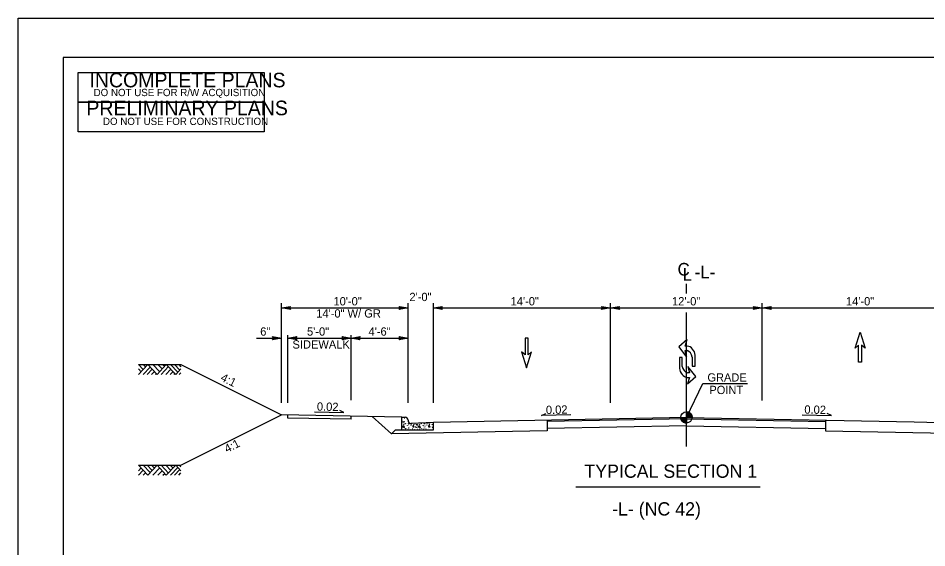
# Model space of a CAD drawing. Extents: x 1901670 to 1902225, y 193498 to 194278.
# Drawn here: x 1901670 to 1901741.8, y 194145.5 to 194187.3 of the extents above; entities that cross this region are included whole.
import ezdxf

# ---------------------------------------------------------------- set-up
doc = ezdxf.new("R2010")
doc.units = 0
for name, color, linetype in [('MARK BIKE LEFT ARROW CELL', 7, 'Continuous'), ('Old_Level_1', 7, 'Continuous'), ('Old_Level_10', 7, 'Continuous'), ('Old_Level_2', 7, 'Continuous'), ('Prop Dimension', 7, 'Continuous'), ('Prop Dimension Text', 7, 'Continuous'), ('Scratch_Level_0', 7, 'Continuous'), ('Sheet Sticker Incomplete CELL', 7, 'Continuous'), ('Sheet Sticker Preliminary CELL', 7, 'Continuous'), ('Typical Curb CELL', 7, 'Continuous'), ('Typical Pavement Slope CELL', 7, 'Continuous'), ('Typical Terminator CELL', 7, 'Continuous'), ('Typical Text Grade Point CELL', 7, 'Continuous')]:
    doc.layers.add(name, color=color, linetype=linetype)

# ---------------------------------------------------------------- blocks, each defined once
blk = doc.blocks.new('TERMINATOR')
at = {"layer": 'Typical Terminator CELL'}
blk.add_lwpolyline([(-0.469, 0.081), (0, 0), (-0.471, -0.083), (-0.411, 0)], close=True, dxfattribs=at)

msp = doc.modelspace()

# ---------------------------------------------------------------- linework, layer by layer
at = {"layer": 'MARK BIKE LEFT ARROW CELL'}
for p, q in [((1901722.83, 194161.908), (1901722.179, 194161.323)), ((1901722.83, 194161.908), (1901722.179, 194161.323)), ((1901722.678, 194161.399), (1901722.83, 194161.908)), ((1901722.678, 194161.399), (1901722.83, 194161.908)), ((1901722.179, 194161.323), (1901722.795, 194160.514)), ((1901722.179, 194161.323), (1901722.795, 194160.514)), ((1901722.852, 194161.4), (1901722.678, 194161.399)), ((1901722.852, 194161.4), (1901722.678, 194161.399)), ((1901722.455, 194160.499), (1901722.224, 194160.499)), ((1901722.224, 194160.499), (1901722.224, 194159.639)), ((1901722.455, 194160.499), (1901722.224, 194160.499)), ((1901722.224, 194160.499), (1901722.224, 194159.639)), ((1901722.455, 194159.793), (1901722.455, 194160.499)), ((1901722.455, 194159.793), (1901722.455, 194160.499)), ((1901722.795, 194160.514), (1901722.678, 194161.034)), ((1901722.678, 194161.034), (1901722.833, 194161.034)), ((1901722.795, 194160.514), (1901722.678, 194161.034)), ((1901722.678, 194161.034), (1901722.833, 194161.034)), ((1901723.244, 194160.515), (1901723.244, 194159.808)), ((1901723.244, 194160.515), (1901723.244, 194159.808)), ((1901723.475, 194159.808), (1901723.475, 194160.669)), ((1901723.475, 194159.808), (1901723.475, 194160.669)), ((1901723.519, 194158.984), (1901722.904, 194159.793)), ((1901722.904, 194159.793), (1901723.02, 194159.273)), ((1901723.519, 194158.984), (1901722.904, 194159.793)), ((1901722.904, 194159.793), (1901723.02, 194159.273)), ((1901723.244, 194159.808), (1901723.475, 194159.808)), ((1901723.244, 194159.808), (1901723.475, 194159.808)), ((1901723.02, 194159.273), (1901722.865, 194159.273)), ((1901723.02, 194159.273), (1901722.865, 194159.273)), ((1901722.869, 194158.399), (1901723.519, 194158.984)), ((1901722.869, 194158.399), (1901723.519, 194158.984)), ((1901722.846, 194158.908), (1901723.02, 194158.908)), ((1901722.846, 194158.908), (1901723.02, 194158.908)), ((1901723.02, 194158.908), (1901722.869, 194158.399)), ((1901723.02, 194158.908), (1901722.869, 194158.399))]:
    msp.add_line(p, q, dxfattribs=at)
for centre, major_axis, ratio in [((1901722.917, 194160.733), (-0.294, 0.632), 0.75825), ((1901722.917, 194160.733), (-0.294, 0.632), 0.75825), ((1901722.897, 194160.579), (-0.204, 0.44), 0.652763), ((1901722.897, 194160.579), (-0.204, 0.44), 0.652763), ((1901722.782, 194159.574), (0.294, -0.632), 0.75825), ((1901722.782, 194159.574), (0.294, -0.632), 0.75825), ((1901722.801, 194159.728), (0.204, -0.44), 0.652763), ((1901722.801, 194159.728), (0.204, -0.44), 0.652763)]:
    msp.add_ellipse(centre, major_axis=major_axis, ratio=ratio, start_param=4.277405, end_param=5.848201, dxfattribs=at)
at = {"layer": 'Old_Level_1'}
for p, q in [((1901722.78, 194165.552), (1901722.78, 194166.32)), ((1901722.78, 194153.466), (1901722.78, 194164.037)), ((1901679.481, 194159.946), (1901679.856, 194159.543)), ((1901679.481, 194159.141), (1901680.223, 194159.938)), ((1901679.855, 194159.141), (1901680.409, 194159.737)), ((1901679.856, 194159.946), (1901680.043, 194159.745)), ((1901680.223, 194159.938), (1901680.947, 194159.159)), ((1901680.614, 194159.946), (1901681.147, 194159.373)), ((1901680.947, 194159.159), (1901681.678, 194159.945)), ((1901681.012, 194159.946), (1901681.345, 194159.587)), ((1901681.257, 194159.141), (1901681.843, 194159.769)), ((1901681.414, 194159.946), (1901681.547, 194159.803)), ((1901681.678, 194159.945), (1901682.419, 194159.149)), ((1901682, 194159.946), (1901682.58, 194159.323)), ((1901682.333, 194159.946), (1901682.747, 194159.502)), ((1901682.653, 194159.946), (1901682.823, 194159.763)), ((1901679.481, 194159.584), (1901679.687, 194159.362)), ((1901680.164, 194159.141), (1901680.565, 194159.57)), ((1901680.511, 194159.141), (1901680.738, 194159.384)), ((1901680.822, 194159.141), (1901680.893, 194159.217)), ((1901681.627, 194159.141), (1901682.027, 194159.57)), ((1901681.993, 194159.141), (1901682.21, 194159.374)), ((1901682.288, 194159.141), (1901682.357, 194159.215)), ((1901682.419, 194159.149), (1901682.823, 194159.584)), ((1901682.689, 194159.141), (1901682.823, 194159.284)), ((1901693.395, 194156.187), (1901695.71, 194156.139)), ((1901695.71, 194156.139), (1901695.377, 194156.306)), ((1901711.327, 194155.904), (1901711.66, 194156.071)), ((1901722.78, 194155.761), (1901722.78, 194156.211)), ((1901734.234, 194155.904), (1901733.901, 194156.071)), ((1901697.952, 194155.824), (1901699.474, 194154.462)), ((1901722.78, 194155.761), (1901702.78, 194155.361)), ((1901713.642, 194155.952), (1901711.327, 194155.904)), ((1901722.782, 194155.657), (1901711.782, 194155.437)), ((1901711.782, 194155.541), (1901711.782, 194154.708)), ((1901722.33, 194155.761), (1901722.78, 194155.761)), ((1901722.779, 194155.311), (1901722.78, 194155.761)), ((1901722.78, 194155.761), (1901722.779, 194155.311)), ((1901723.23, 194155.761), (1901722.78, 194155.761)), ((1901722.78, 194155.761), (1901740.78, 194155.401)), ((1901722.782, 194155.657), (1901733.782, 194155.437)), ((1901731.919, 194155.952), (1901734.234, 194155.904)), ((1901733.782, 194155.541), (1901733.782, 194154.708)), ((1901740.78, 194155.401), (1901742.78, 194155.361)), ((1901699.781, 194154.768), (1901699.474, 194154.462)), ((1901711.782, 194154.708), (1901699.474, 194154.462)), ((1901699.781, 194154.768), (1901700.281, 194154.778)), ((1901722.782, 194155.095), (1901711.782, 194154.875)), ((1901722.782, 194155.095), (1901733.782, 194154.875)), ((1901733.782, 194154.708), (1901746.086, 194154.462)), ((1901679.481, 194151.989), (1901680.223, 194151.192)), ((1901679.481, 194151.546), (1901679.687, 194151.768)), ((1901679.855, 194151.989), (1901680.409, 194151.393)), ((1901680.164, 194151.989), (1901680.565, 194151.56)), ((1901680.223, 194151.192), (1901680.947, 194151.971)), ((1901680.511, 194151.989), (1901680.738, 194151.746)), ((1901680.614, 194151.184), (1901681.147, 194151.757)), ((1901680.822, 194151.989), (1901680.893, 194151.913)), ((1901680.947, 194151.971), (1901681.678, 194151.185)), ((1901681.257, 194151.989), (1901681.843, 194151.361)), ((1901681.627, 194151.989), (1901682.027, 194151.56)), ((1901681.678, 194151.185), (1901682.419, 194151.981)), ((1901681.993, 194151.989), (1901682.21, 194151.756)), ((1901682, 194151.184), (1901682.58, 194151.807)), ((1901682.288, 194151.989), (1901682.357, 194151.915)), ((1901682.419, 194151.981), (1901682.823, 194151.546)), ((1901682.689, 194151.989), (1901682.823, 194151.846)), ((1901679.481, 194151.184), (1901679.856, 194151.587)), ((1901679.856, 194151.184), (1901680.043, 194151.385)), ((1901681.012, 194151.184), (1901681.345, 194151.543)), ((1901681.414, 194151.184), (1901681.547, 194151.327)), ((1901682.333, 194151.184), (1901682.747, 194151.628)), ((1901682.653, 194151.184), (1901682.823, 194151.367)), ((1901714.048, 194150.258), (1901728.608, 194150.258))]:
    msp.add_line(p, q, dxfattribs=at)
for points in [[(1901722.784, 194156.211), (1901722.784, 194156.211), (1901722.784, 194155.761)], [(1901722.793, 194156.211), (1901722.793, 194155.761)], [(1901722.802, 194156.21), (1901722.802, 194155.761)], [(1901722.811, 194156.21), (1901722.811, 194155.761)], [(1901722.82, 194156.209), (1901722.82, 194155.761)], [(1901722.829, 194156.208), (1901722.829, 194155.761)], [(1901722.838, 194156.207), (1901722.838, 194155.761)], [(1901722.847, 194156.206), (1901722.847, 194155.761)], [(1901722.856, 194156.205), (1901722.856, 194155.761)], [(1901722.865, 194156.203), (1901722.865, 194155.761)], [(1901722.874, 194156.201), (1901722.874, 194155.761)], [(1901722.883, 194156.199), (1901722.883, 194155.761)], [(1901722.892, 194156.197), (1901722.892, 194155.761)], [(1901722.901, 194156.194), (1901722.901, 194155.761)], [(1901722.91, 194156.192), (1901722.91, 194155.761)], [(1901722.919, 194156.189), (1901722.919, 194155.761)], [(1901722.928, 194156.186), (1901722.928, 194155.761)], [(1901722.937, 194156.183), (1901722.937, 194155.761)], [(1901722.946, 194156.179), (1901722.946, 194155.761)], [(1901722.955, 194156.175), (1901722.955, 194155.761)], [(1901722.964, 194156.171), (1901722.964, 194155.761)], [(1901722.973, 194156.167), (1901722.973, 194155.761)], [(1901722.982, 194156.163), (1901722.982, 194155.761)], [(1901722.991, 194156.158), (1901722.991, 194155.761)], [(1901723, 194156.153), (1901723, 194155.761)], [(1901723.009, 194156.148), (1901723.009, 194155.761)], [(1901723.018, 194156.143), (1901723.018, 194155.761)], [(1901723.027, 194156.137), (1901723.027, 194155.761)], [(1901723.036, 194156.131), (1901723.036, 194155.761)], [(1901723.045, 194156.124), (1901723.045, 194155.761)], [(1901723.054, 194156.118), (1901723.054, 194155.761)], [(1901723.063, 194156.111), (1901723.063, 194155.761)], [(1901723.072, 194156.103), (1901723.072, 194155.761)], [(1901723.081, 194156.095), (1901723.081, 194155.761)], [(1901723.09, 194156.087), (1901723.09, 194155.761)], [(1901723.099, 194156.078), (1901723.099, 194155.761)], [(1901723.108, 194156.069), (1901723.108, 194155.761)], [(1901723.117, 194156.059), (1901723.117, 194155.761)], [(1901723.126, 194156.048), (1901723.126, 194155.761)], [(1901722.332, 194155.761), (1901722.332, 194155.712)], [(1901722.341, 194155.761), (1901722.341, 194155.659)], [(1901722.35, 194155.761), (1901722.35, 194155.627)], [(1901722.359, 194155.761), (1901722.359, 194155.6)], [(1901722.368, 194155.761), (1901722.368, 194155.579)], [(1901722.377, 194155.761), (1901722.377, 194155.56)], [(1901722.386, 194155.761), (1901722.386, 194155.543)], [(1901722.395, 194155.761), (1901722.395, 194155.527)], [(1901722.404, 194155.761), (1901722.404, 194155.513)], [(1901722.413, 194155.761), (1901722.413, 194155.5)], [(1901722.422, 194155.761), (1901722.422, 194155.488)], [(1901722.431, 194155.761), (1901722.431, 194155.477)], [(1901722.44, 194155.761), (1901722.44, 194155.466)], [(1901722.449, 194155.761), (1901722.449, 194155.456)], [(1901722.458, 194155.761), (1901722.458, 194155.446)], [(1901722.467, 194155.761), (1901722.467, 194155.437)], [(1901722.476, 194155.761), (1901722.476, 194155.429)], [(1901722.485, 194155.761), (1901722.485, 194155.421)], [(1901722.494, 194155.761), (1901722.494, 194155.413)], [(1901722.503, 194155.761), (1901722.503, 194155.406)], [(1901722.512, 194155.761), (1901722.512, 194155.399)], [(1901722.521, 194155.761), (1901722.521, 194155.393)], [(1901722.53, 194155.761), (1901722.53, 194155.387)], [(1901722.539, 194155.761), (1901722.539, 194155.381)], [(1901722.548, 194155.761), (1901722.548, 194155.375)], [(1901722.557, 194155.761), (1901722.557, 194155.37)], [(1901722.566, 194155.761), (1901722.566, 194155.365)], [(1901722.575, 194155.761), (1901722.575, 194155.36)], [(1901722.584, 194155.761), (1901722.584, 194155.356)], [(1901722.593, 194155.761), (1901722.593, 194155.352)], [(1901722.602, 194155.761), (1901722.602, 194155.348)], [(1901722.611, 194155.761), (1901722.611, 194155.344)], [(1901722.62, 194155.761), (1901722.62, 194155.34)], [(1901722.629, 194155.761), (1901722.629, 194155.337)], [(1901722.638, 194155.761), (1901722.638, 194155.334)], [(1901722.647, 194155.761), (1901722.647, 194155.331)], [(1901722.656, 194155.761), (1901722.656, 194155.329)], [(1901722.665, 194155.761), (1901722.665, 194155.326)], [(1901722.674, 194155.761), (1901722.674, 194155.324)], [(1901722.683, 194155.761), (1901722.683, 194155.322)], [(1901722.692, 194155.761), (1901722.692, 194155.32)], [(1901722.701, 194155.761), (1901722.701, 194155.318)], [(1901722.71, 194155.761), (1901722.71, 194155.317)], [(1901722.719, 194155.761), (1901722.719, 194155.315)], [(1901722.728, 194155.761), (1901722.728, 194155.314)], [(1901722.737, 194155.761), (1901722.737, 194155.313)], [(1901722.746, 194155.761), (1901722.746, 194155.312)], [(1901722.755, 194155.761), (1901722.755, 194155.312)], [(1901722.764, 194155.761), (1901722.764, 194155.311)], [(1901722.773, 194155.761), (1901722.773, 194155.311), (1901722.773, 194155.311)], [(1901723.135, 194156.037), (1901723.135, 194155.761)], [(1901723.144, 194156.025), (1901723.144, 194155.761)], [(1901723.153, 194156.012), (1901723.153, 194155.761)], [(1901723.162, 194155.998), (1901723.162, 194155.761)], [(1901723.171, 194155.983), (1901723.171, 194155.761)], [(1901723.18, 194155.967), (1901723.18, 194155.761)], [(1901723.189, 194155.948), (1901723.189, 194155.761)], [(1901723.198, 194155.927), (1901723.198, 194155.761)], [(1901723.207, 194155.902), (1901723.207, 194155.761)], [(1901723.216, 194155.871), (1901723.216, 194155.761)], [(1901723.225, 194155.825), (1901723.225, 194155.761)]]:
    msp.add_lwpolyline(points, dxfattribs=at)
msp.add_circle((1901722.78, 194155.761), 0.45, dxfattribs=at)
for start, end in [(359.99048, 89.99048), (179.99048, 269.99048)]:
    msp.add_arc((1901722.78, 194155.761), 0.45, start, end, dxfattribs=at)
at = {"layer": 'Old_Level_10'}
msp.add_lwpolyline([(1901673.525, 194104.872), (1901776.645, 194104.872), (1901776.645, 194184.208), (1901673.525, 194184.208)], close=True, dxfattribs=at)
at = {"layer": 'Prop Dimension'}
for p, q in [((1901690.78, 194156.899), (1901690.78, 194164.781)), ((1901700.78, 194156.899), (1901700.78, 194164.781)), ((1901702.78, 194156.899), (1901702.78, 194164.781)), ((1901716.78, 194156.899), (1901716.78, 194164.781)), ((1901728.78, 194157.09), (1901728.78, 194164.781)), ((1901690.78, 194164.411), (1901700.78, 194164.411)), ((1901702.78, 194164.411), (1901716.78, 194164.411)), ((1901716.78, 194164.411), (1901728.78, 194164.411)), ((1901728.78, 194164.411), (1901742.78, 194164.411)), ((1901688.815, 194162.021), (1901690.78, 194162.021)), ((1901691.28, 194156.899), (1901691.28, 194162.248)), ((1901691.28, 194162.021), (1901696.28, 194162.021)), ((1901696.28, 194157.12), (1901696.28, 194162.248)), ((1901696.28, 194162.021), (1901700.78, 194162.021))]:
    msp.add_line(p, q, dxfattribs=at)
for points in [[(1901710.545, 194160.941), (1901710.274, 194160.691), (1901710.274, 194162.025), (1901710.024, 194162.025), (1901710.024, 194160.691), (1901709.753, 194160.941), (1901710.149, 194159.67)], [(1901710.545, 194160.941), (1901710.274, 194160.691), (1901710.274, 194162.025), (1901710.024, 194162.025), (1901710.024, 194160.691), (1901709.753, 194160.941), (1901710.149, 194159.67)], [(1901736.901, 194161.22), (1901736.63, 194161.47), (1901736.63, 194160.136), (1901736.38, 194160.136), (1901736.38, 194161.47), (1901736.11, 194161.22), (1901736.505, 194162.49)], [(1901736.901, 194161.22), (1901736.63, 194161.47), (1901736.63, 194160.136), (1901736.38, 194160.136), (1901736.38, 194161.47), (1901736.11, 194161.22), (1901736.505, 194162.49)]]:
    msp.add_lwpolyline(points, close=True, dxfattribs=at)
at = {"layer": 'Scratch_Level_0'}
msp.add_lwpolyline([(1901669.969, 194187.31), (1901779.969, 194187.31), (1901779.969, 194102.31), (1901669.969, 194102.31)], close=True, dxfattribs=at)
at = {"layer": 'Sheet Sticker Incomplete CELL'}
msp.add_lwpolyline([(1901674.711, 194180.674), (1901674.711, 194183.024), (1901689.411, 194183.024), (1901689.411, 194180.674)], close=True, dxfattribs=at)
at = {"layer": 'Sheet Sticker Preliminary CELL'}
msp.add_lwpolyline([(1901674.711, 194178.324), (1901674.711, 194180.674), (1901689.411, 194180.674), (1901689.411, 194178.324)], close=True, dxfattribs=at)
at = {"layer": 'Typical Curb CELL'}
for p, q in [((1901700.281, 194154.778), (1901700.281, 194155.778)), ((1901700.281, 194155.778), (1901700.541, 194155.778)), ((1901700.317, 194155.4), (1901700.471, 194155.445)), ((1901700.455, 194155.354), (1901700.317, 194155.4)), ((1901700.471, 194155.445), (1901700.455, 194155.354)), ((1901700.781, 194155.528), (1901700.781, 194155.538)), ((1901702.78, 194155.361), (1901701.03, 194155.288)), ((1901702.78, 194154.778), (1901702.78, 194155.361)), ((1901700.281, 194154.778), (1901702.78, 194154.778)), ((1901700.443, 194155.081), (1901700.34, 194155.006)), ((1901700.34, 194155.006), (1901700.506, 194154.966)), ((1901700.506, 194154.966), (1901700.443, 194155.081)), ((1901701.185, 194155.137), (1901701.15, 194155.024)), ((1901701.15, 194155.024), (1901701.27, 194155.018)), ((1901701.27, 194155.018), (1901701.185, 194155.137)), ((1901701.692, 194155.081), (1901701.589, 194155.006)), ((1901701.589, 194155.006), (1901701.754, 194154.966)), ((1901701.754, 194154.966), (1901701.692, 194155.081)), ((1901702.433, 194155.137), (1901702.399, 194155.024)), ((1901702.399, 194155.024), (1901702.52, 194155.018)), ((1901702.52, 194155.018), (1901702.433, 194155.137))]:
    msp.add_line(p, q, dxfattribs=at)
for centre in [(1901700.294, 194155.668), (1901700.345, 194155.485), (1901700.511, 194155.702), (1901702.439, 194155.32), (1901700.425, 194154.824), (1901700.442, 194155.212), (1901700.562, 194155.263), (1901700.597, 194154.864), (1901700.739, 194155.098), (1901700.774, 194154.801), (1901700.819, 194155.291), (1901700.831, 194154.915), (1901700.836, 194155.241), (1901700.865, 194155.069), (1901700.945, 194154.83), (1901701.013, 194155.155), (1901701.042, 194155.257), (1901701.15, 194154.852), (1901701.236, 194155.218), (1901701.31, 194154.784), (1901701.333, 194155.272), (1901701.361, 194155.018), (1901701.442, 194155.178), (1901701.458, 194154.972), (1901701.498, 194155.212), (1901701.515, 194155.115), (1901701.52, 194154.807), (1901701.674, 194154.824), (1901701.692, 194155.212), (1901701.812, 194155.263), (1901701.846, 194154.864), (1901701.988, 194155.098), (1901702.023, 194154.801), (1901702.068, 194155.291), (1901702.08, 194154.915), (1901702.085, 194155.241), (1901702.114, 194155.069), (1901702.194, 194154.83), (1901702.262, 194155.155), (1901702.291, 194155.257), (1901702.399, 194154.852), (1901702.485, 194155.218), (1901702.559, 194154.784), (1901702.582, 194155.303), (1901702.611, 194155.018), (1901702.691, 194155.178), (1901702.707, 194154.972), (1901702.747, 194155.212), (1901702.764, 194155.115), (1901702.769, 194154.807)]:
    msp.add_circle(centre, 0.00802, dxfattribs=at)
for centre, start, end in [((1901700.541, 194155.538), 0.00016, 90.00016), ((1901701.02, 194155.528), 180.00016, 272.38461)]:
    msp.add_arc(centre, 0.24, start, end, dxfattribs=at)
at = {"layer": 'Typical Pavement Slope CELL'}
for p, q in [((1901682.823, 194159.946), (1901690.78, 194155.968)), ((1901682.823, 194151.989), (1901690.78, 194155.968)), ((1901700.281, 194155.778), (1901690.78, 194155.968)), ((1901691.28, 194155.708), (1901691.28, 194155.958)), ((1901696.28, 194155.608), (1901691.28, 194155.708)), ((1901696.28, 194155.608), (1901696.28, 194155.858))]:
    msp.add_line(p, q, dxfattribs=at)
for points in [[(1901679.481, 194159.946), (1901682.823, 194159.946)], [(1901679.481, 194151.989), (1901682.823, 194151.989)]]:
    msp.add_lwpolyline(points, dxfattribs=at)
at = {"layer": 'Typical Text Grade Point CELL'}
for p, q in [((1901722.78, 194155.761), (1901724.076, 194158.434)), ((1901724.076, 194158.434), (1901727.614, 194158.434))]:
    msp.add_line(p, q, dxfattribs=at)

# ---------------------------------------------------------------- block references
at = {"layer": 'Prop Dimension', "xscale": 1.5, "yscale": 1.5, "rotation": 180}
for p in [(1901690.78, 194164.411), (1901702.78, 194164.411), (1901716.78, 194164.411), (1901728.78, 194164.411), (1901691.28, 194162.021), (1901696.28, 194162.021)]:
    msp.add_blockref('TERMINATOR', p, dxfattribs=at)
at = {"layer": 'Prop Dimension', "xscale": 1.5, "yscale": 1.5}
for p in [(1901700.78, 194164.411), (1901716.78, 194164.411), (1901728.78, 194164.411), (1901690.78, 194162.021), (1901696.28, 194162.021), (1901700.78, 194162.021)]:
    msp.add_blockref('TERMINATOR', p, dxfattribs=at)

# ---------------------------------------------------------------- texts
at = {"layer": 'Old_Level_1'}
for rotation, p in [(333.43495, (1901685.906, 194158.695)), (26.56505, (1901686.472, 194152.94))]:
    msp.add_text('4:1', height=0.656, rotation=rotation, dxfattribs=at).set_placement(p)
msp.add_text('TYPICAL SECTION 1', height=1.05, dxfattribs=at).set_placement((1901714.717, 194150.984))
at = {"layer": 'Old_Level_2'}
msp.add_text('C', height=1, dxfattribs=at).set_placement((1901722.079, 194166.966))
for s, height, rotation, p in [('L', 1, 359.9469, (1901722.481, 194166.562)), ('-L-', 1, 359.9469, (1901723.429, 194166.745)), ('0.02', 0.656, 358.80842, (1901693.572, 194156.294)), ('0.02', 0.656, 1.19158, (1901711.682, 194156.022)), ('0.02', 0.656, 358.80842, (1901732.096, 194156.059))]:
    msp.add_text(s, height=height, rotation=rotation, dxfattribs=at).set_placement(p)
at = {"layer": 'Prop Dimension'}
for s, p in [('2\'-0" ', (1901700.889, 194164.95)), ('10\'-0" ', (1901694.887, 194164.609)), ('14\'-0" ', (1901708.887, 194164.609)), ('12\'-0" ', (1901721.643, 194164.609)), ('14\'-0" ', (1901735.388, 194164.609)), ('14\'-0" W/ GR ', (1901693.525, 194163.649)), ('6" ', (1901689.097, 194162.219)), ('5\'-0" ', (1901692.798, 194162.219)), ('4\'-6" ', (1901697.658, 194162.219)), ('SIDEWALK', (1901691.647, 194161.198))]:
    msp.add_text(s, height=0.656, dxfattribs=at).set_placement(p)
at = {"layer": 'Prop Dimension Text'}
msp.add_text('-L- (NC 42) ', height=1.05, dxfattribs=at).set_placement((1901716.907, 194148.004))
at = {"layer": 'Sheet Sticker Incomplete CELL'}
for s, height, p in [('INCOMPLETE PLANS', 1.152, (1901675.606, 194181.844)), ('DO NOT USE FOR R/W ACQUISITION', 0.576, (1901675.931, 194181.149))]:
    msp.add_text(s, height=height, dxfattribs=at).set_placement(p)
at = {"layer": 'Sheet Sticker Preliminary CELL'}
for s, height, p in [('PRELIMINARY PLANS', 1.152, (1901675.361, 194179.639)), ('DO NOT USE FOR CONSTRUCTION', 0.576, (1901676.671, 194178.869))]:
    msp.add_text(s, height=height, dxfattribs=at).set_placement(p)
at = {"layer": 'Typical Text Grade Point CELL'}
for s, p in [('GRADE', (1901724.44, 194158.59)), ('POINT', (1901724.597, 194157.602))]:
    msp.add_text(s, height=0.6525, dxfattribs=at).set_placement(p)

doc.saveas('drawing.dxf')
